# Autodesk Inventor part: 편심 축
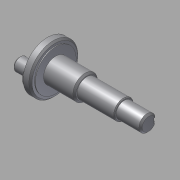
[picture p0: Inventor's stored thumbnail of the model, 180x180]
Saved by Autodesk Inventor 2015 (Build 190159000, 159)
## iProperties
Created: 2015-10
Part Number: 편심 축
Document SubType Name: Modeling
Designer: mdu
Density: 7.86 g/cm^3
Material: 강철, 연강
Mass: 86.2323 g
Surface Area: 42.7652 cm^2
Volume: 10.971 cm^3
Appearance: 기본값
Author: mdu
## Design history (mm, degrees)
sketch "스케치1"
  geometry: L1 (1.75, -12.001)-(1.75, 11.999) reference; L2 (-16.95, -14)-(-16.95, 14) reference; L3 (-36.25, -18.06)-(-36.25, 18.06) reference; L4 (-41.25, 0)-(20.75, 0); L5 (-41.25, 0)-(-41.25, 15); L6 (-41.25, 15)-(-36.25, 15); L7 (-36.25, 15)-(-36.25, 7.5); L8 (-36.25, 7.5)-(-17.25, 7.5); L9 (-17.25, 6)-(5.75, 6); L10 (20.75, 5)-(20.75, 0); L11 (5.75, 6)-(5.75, 5); L12 (5.75, 5)-(20.75, 5); L13 (-17.25, -13.7)-(-17.25, 13.7) reference; L14 (-17.25, 7.5)-(-17.25, 6); 2 further points
  constraints: 20 end point, 7 perpendicular, 5 point on line, 1 collinear, 1 midpoint, 1 parallel
  dimensions: "d0" = 12 diameter of L9 L4; "d1" = 15 diameter of L8 L4; "d2" = 30 diameter of L6 L4; "d3" = 5 distance of L5.end L6.end; "d4" = 62 distance of L4.start L4.end; "d5" = 10 diameter of L12 L4; "d6" = 15 distance of L11.end L10.start
revolve "회전1" sketch "스케치1" stored, may be unused: angle "d7" = 90 deg
sketch "스케치4"
  geometry: C1 r 15 at (0, 0) reference; C2 r 12.5 at (0, 0); 1 further point
  constraints: 1 centre point, 1 coincident
  dimensions: "d24" = 25 diameter of C2
extrude "돌출4" cut sketch "스케치4" distance "d25" = 0.5; taper "d26" = 0 deg
sketch "스케치2"
  geometry: C1 r 4 at (0, -7.5); C2 r 7.5 at (0, -7.5); C3 r 15 at (0, 0) reference; 1 further point
  constraints: 2 centre point, 1 coincident, 1 tangent, 1 vertical alignment
  dimensions: "d8" = 8 diameter of C1; "d9" = 7.5 distance of point (0, 0) C1.centre
extrude "돌출1" join sketch "스케치2" distance "d10" = 10; taper "d11" = 0 deg
extrude "돌출2" join sketch "스케치2" distance "d12" = 0.5; taper "d13" = 0 deg
node "작업 평면1"
sketch "스케치3"
  geometry: L1 (-7.5, 5)-(-7.5, -5) reference; L2 (-7.5, 1.5)-(3, 1.5); L3 (3, -1.5)-(-7.5, -1.5); A1 r 1.5 centre (3, 0) between (3, -1.5) and (3, 1.5); 2 further points
  constraints: 4 end point, 2 perpendicular, 2 point on circle, 2 point on line, 2 tangent, 1 centre point, 1 horizontal alignment, 1 midpoint
  dimensions: "d14" = 3 distance between parallel lines of L3 L2; "d15" = 12 dimension on A1 L1
extrude "돌출3" cut sketch "스케치3" distance "d16" = 1.8; taper "d17" = 0 deg
chamfer "모따기1" distance "d18" = 1; stored, may be unused: second distance "d19" = 2, angle "d20" = 45 deg
chamfer "모따기2" distance "d21" = 0.5; stored, may be unused: second distance "d22" = 2, angle "d23" = 45 deg
node "솔리드1"
node "참조1"
node "참조2"
node "참조3"
node "참조4"
